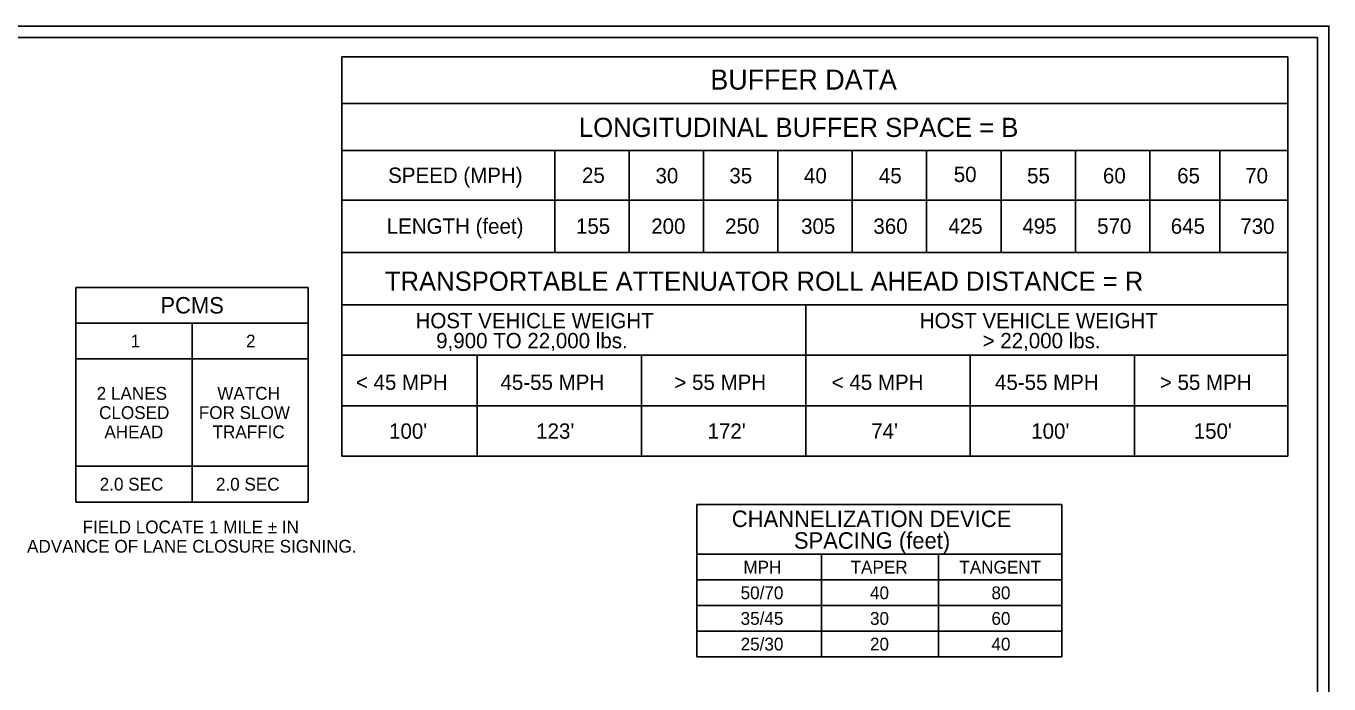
# Model space of a CAD drawing. Extents: x 99988 to 100172, y 99995 to 100047.
# Drawn here: x 100008.68 to 100015.81, y 100006.84 to 100010.44 of the extents above; entities that cross this region are included whole.
import ezdxf

# ---------------------------------------------------------------- set-up
doc = ezdxf.new("R2010")
doc.units = 0
for name, color, linetype in [('SH_DE_DetailBody1Text', 7, 'Continuous'), ('SH_GI_PlotLimits', 7, 'Continuous'), ('SH_GI_SheetBorder', 7, 'Continuous'), ('SH_TI_BufferDataNote', 7, 'Continuous'), ('SH_TI_ChanSpacing25to70Note', 7, 'Continuous'), ('SH_TI_MinTaperLength25to35Note', 7, 'Continuous'), ('TR_WZ_WorkZoneDetails', 7, 'Continuous')]:
    doc.layers.add(name, color=color, linetype=linetype)

msp = doc.modelspace()

# ---------------------------------------------------------------- linework, layer by layer
at = {"layer": 'SH_GI_PlotLimits'}
msp.add_lwpolyline([(99999.3125, 99999.9375), (100015.8125, 99999.9375), (100015.8125, 100010.4375), (99999.3125, 100010.4375)], close=True, dxfattribs=at)
at = {"layer": 'SH_GI_SheetBorder'}
for p, q in [((100000, 100010.375), (100015.75, 100010.375)), ((100015.75, 100010.375), (100015.75, 100000))]:
    msp.add_line(p, q, dxfattribs=at)
at = {"layer": 'SH_TI_BufferDataNote'}
for p, q in [((100010.4058, 100010.0134), (100015.5874, 100010.0134)), ((100010.4058, 100009.7562), (100015.5874, 100009.7562)), ((100011.5713, 100009.7562), (100011.5713, 100009.1989)), ((100011.9788, 100009.7562), (100011.9788, 100009.1989)), ((100012.3863, 100009.7562), (100012.3863, 100009.1989)), ((100012.7938, 100009.7562), (100012.7938, 100009.1989)), ((100013.2013, 100009.7562), (100013.2013, 100009.1989)), ((100013.6088, 100009.7562), (100013.6088, 100009.1989)), ((100014.0163, 100009.7562), (100014.0163, 100009.1989)), ((100014.4238, 100009.7562), (100014.4238, 100009.1989)), ((100014.8312, 100009.7562), (100014.8312, 100009.1989)), ((100015.2141, 100009.7562), (100015.2141, 100009.1989)), ((100010.4058, 100009.484), (100015.5874, 100009.484)), ((100010.4058, 100009.1989), (100015.5874, 100009.1989)), ((100010.4058, 100008.9118), (100015.5874, 100008.9118)), ((100012.9463, 100008.0838), (100012.9463, 100008.9094)), ((100010.4058, 100008.6358), (100015.5874, 100008.6358)), ((100011.1465, 100008.0838), (100011.1465, 100008.6358)), ((100012.0465, 100008.0838), (100012.0465, 100008.6358)), ((100012.9465, 100008.0838), (100012.9465, 100008.6358)), ((100013.8465, 100008.0838), (100013.8465, 100008.6358)), ((100014.7465, 100008.0838), (100014.7465, 100008.6358)), ((100010.4058, 100008.3598), (100015.5874, 100008.3598))]:
    msp.add_line(p, q, dxfattribs=at)
at = {"layer": 'SH_TI_ChanSpacing25to70Note'}
for p, q in [((100012.3494, 100007.819), (100012.3494, 100006.9846)), ((100012.3494, 100007.819), (100014.3494, 100007.819)), ((100014.3494, 100007.819), (100014.3494, 100006.9846)), ((100012.3494, 100007.5461), (100014.3494, 100007.5461)), ((100013.0321, 100006.9846), (100013.0321, 100007.5461)), ((100013.6741, 100006.9846), (100013.6741, 100007.5461)), ((100012.3494, 100007.4057), (100014.3494, 100007.4057)), ((100012.3494, 100007.2654), (100014.3494, 100007.2654)), ((100012.3494, 100007.125), (100014.3494, 100007.125)), ((100012.3494, 100006.9846), (100014.3494, 100006.9846))]:
    msp.add_line(p, q, dxfattribs=at)
at = {"layer": 'SH_TI_MinTaperLength25to35Note'}
for p, q in [((100010.4058, 100010.2684), (100015.5874, 100010.2684)), ((100010.4058, 100008.0838), (100010.4058, 100010.2684)), ((100015.5874, 100008.0838), (100015.5874, 100010.2684)), ((100010.4058, 100008.0838), (100015.5874, 100008.0838))]:
    msp.add_line(p, q, dxfattribs=at)
at = {"layer": 'TR_WZ_WorkZoneDetails'}
for p, q in [((100008.9481, 100009.0072), (100010.2213, 100009.0072)), ((100008.9481, 100007.832), (100008.9481, 100009.0072)), ((100010.2213, 100007.832), (100010.2213, 100009.0072)), ((100010.2213, 100008.8114), (100008.9481, 100008.8114)), ((100009.5847, 100007.832), (100009.5847, 100008.8114)), ((100010.2213, 100008.6155), (100008.9481, 100008.6155)), ((100008.9481, 100008.0279), (100010.2213, 100008.0279)), ((100010.2213, 100007.832), (100008.9481, 100007.832))]:
    msp.add_line(p, q, dxfattribs=at)

# ---------------------------------------------------------------- texts
at = {"layer": 'SH_DE_DetailBody1Text'}
for s, height, p in [('PCMS', 0.09, (100009.4113, 100008.8643)), ('1', 0.07, (100009.2484, 100008.6784)), ('2', 0.07, (100009.8804, 100008.6784)), ('2 LANES', 0.07, (100009.0624, 100008.3922)), ('WATCH', 0.07, (100009.723, 100008.3924)), ('CLOSED', 0.07, (100009.0756, 100008.2867)), ('FOR SLOW', 0.07, (100009.6219, 100008.2869)), ('AHEAD', 0.07, (100009.1047, 100008.1811)), ('TRAFFIC', 0.07, (100009.6972, 100008.1813)), ('2.0 SEC', 0.07, (100009.079, 100007.8949)), ('2.0 SEC', 0.07, (100009.7156, 100007.8949)), ('FIELD LOCATE 1 MILE ± IN', 0.07, (100008.9852, 100007.6608)), ('ADVANCE OF LANE CLOSURE SIGNING.', 0.07, (100008.6809, 100007.5552))]:
    msp.add_text(s, height=height, dxfattribs=at).set_placement(p)
at = {"layer": 'SH_TI_BufferDataNote'}
for s, height, p in [('BUFFER DATA', 0.11, (100012.4241, 100010.0897)), ('LONGITUDINAL BUFFER SPACE = B', 0.105, (100011.704, 100009.8306)), ('SPEED (MPH)', 0.084, (100010.6589, 100009.579)), ('25', 0.084, (100011.7208, 100009.579)), ('30', 0.084, (100012.1234, 100009.5767)), ('35', 0.084, (100012.5281, 100009.5767)), ('40', 0.084, (100012.9369, 100009.5767)), ('45', 0.084, (100013.3471, 100009.5767)), ('50', 0.084, (100013.7573, 100009.5838)), ('55', 0.084, (100014.159, 100009.5767)), ('60', 0.084, (100014.5746, 100009.5767)), ('65', 0.084, (100014.981, 100009.5767)), ('70', 0.084, (100015.3538, 100009.5767)), ('LENGTH (feet)', 0.084, (100010.6512, 100009.3004)), ('155', 0.084, (100011.6878, 100009.3004)), ('200', 0.084, (100012.1, 100009.3004)), ('250', 0.084, (100012.5049, 100009.3004)), ('305', 0.084, (100012.921, 100009.3004)), ('360', 0.084, (100013.317, 100009.3004)), ('425', 0.084, (100013.7281, 100009.3004)), ('495', 0.084, (100014.1333, 100009.3004)), ('570', 0.084, (100014.5427, 100009.3004)), ('645', 0.084, (100014.9461, 100009.3004)), ('730', 0.084, (100015.3271, 100009.3004)), ('TRANSPORTABLE ATTENUATOR ROLL AHEAD DISTANCE = R', 0.105, (100010.641, 100008.9886)), ('HOST VEHICLE WEIGHT', 0.084, (100010.8092, 100008.7832)), ('HOST VEHICLE WEIGHT', 0.084, (100013.5711, 100008.7832)), ('9,900 TO 22,000 lbs.', 0.084, (100010.9221, 100008.6738)), ('> 22,000 lbs.', 0.084, (100013.9155, 100008.6738)), ('< 45 MPH', 0.084, (100010.4823, 100008.446)), ('45-55 MPH', 0.084, (100011.2743, 100008.446)), ('> 55 MPH', 0.084, (100012.2269, 100008.446)), ('< 45 MPH', 0.084, (100013.0889, 100008.446)), ('45-55 MPH', 0.084, (100013.9832, 100008.446)), ('> 55 MPH', 0.084, (100014.8862, 100008.446)), ("100'", 0.084, (100010.6641, 100008.1788)), ("123'", 0.084, (100011.4699, 100008.1788)), ("172'", 0.084, (100012.4087, 100008.1788)), ("74'", 0.084, (100013.3053, 100008.1788)), ("100'", 0.084, (100014.1816, 100008.1788)), ("150'", 0.084, (100015.072, 100008.1788))]:
    msp.add_text(s, height=height, dxfattribs=at).set_placement(p)
at = {"layer": 'SH_TI_ChanSpacing25to70Note'}
for s, height, p in [('CHANNELIZATION DEVICE', 0.09, (100012.5415, 100007.6957)), ('SPACING (feet)', 0.09, (100012.8817, 100007.5769)), ('MPH', 0.07, (100012.6051, 100007.4409)), ('TAPER', 0.07, (100013.1924, 100007.4409)), ('TANGENT', 0.07, (100013.7881, 100007.4409)), ('50/70', 0.07, (100012.5898, 100007.3005)), ('40', 0.07, (100013.2985, 100007.3005)), ('80', 0.07, (100013.9637, 100007.3005)), ('35/45', 0.07, (100012.5898, 100007.1602)), ('30', 0.07, (100013.2985, 100007.1602)), ('60', 0.07, (100013.9637, 100007.1602)), ('25/30', 0.07, (100012.5899, 100007.0198)), ('20', 0.07, (100013.2985, 100007.0198)), ('40', 0.07, (100013.9637, 100007.0198))]:
    msp.add_text(s, height=height, dxfattribs=at).set_placement(p)

doc.saveas('drawing.dxf')
